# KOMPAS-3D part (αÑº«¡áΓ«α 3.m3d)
File: created 29.01.2016 13:47:21, last saved 27.07.2016 10:07:17.
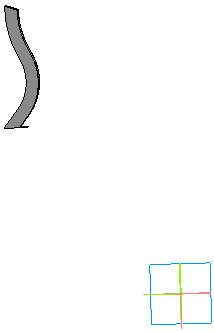
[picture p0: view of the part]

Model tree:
1. Эскиз:1
2. Операция выдавливания:1
     Толщина стенки 1 = 2; Толщина стенки 2 = 8; Расстояние 1 = 1
3. Эскиз:2
4. Операция выдавливания:2
     Толщина стенки 1 = 2; Толщина стенки 2 = 8; Расстояние 1 = 5
5. Эскиз:3
6. Операция выдавливания:3
     Толщина стенки 1 = 2; Толщина стенки 2 = 8; Расстояние 1 = 1
7. Эскиз:4
8. Операция выдавливания:4
     Толщина стенки 1 = 2; Толщина стенки 2 = 2.5; Расстояние 1 = 50
9. Эскиз:5
10. Вырезать элемент выдавливания:1
     Толщина стенки 2 = 1.2; Расстояние 1 = 40
11. Эскиз:6
12. Операция выдавливания:5
     Толщина стенки 1 = 2; Толщина стенки 2 = 2.5; Расстояние 1 = 10
13. Эскиз:7
14. Операция выдавливания:6
     Толщина стенки 1 = 2; Толщина стенки 2 = 8; Расстояние 1 = 1
15. Эскиз:8
16. Операция выдавливания:7
     Толщина стенки 1 = 2; Толщина стенки 2 = 8; Расстояние 1 = 5
17. Эскиз:9
18. Операция выдавливания:8
     Толщина стенки 1 = 2; Толщина стенки 2 = 8; Расстояние 1 = 1
19. Эскиз:10
20. Вырезать элемент выдавливания:2
     Толщина стенки 2 = 1.2; Расстояние 1 = 23
21. Эскиз:11
22. Вырезать элемент выдавливания:3
     Толщина стенки 2 = 1.2; Расстояние 1 = 1
23. Эскиз:12
24. Вырезать элемент выдавливания:4
     Расстояние 1 = 100
25. Эскиз:14
26. Операция выдавливания:10
     Расстояние 1 = 10; Расстояние 2 = 0.4
27. Эскиз:16
28. Операция выдавливания:12
     Расстояние 1 = 10; Расстояние 2 = 0.4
